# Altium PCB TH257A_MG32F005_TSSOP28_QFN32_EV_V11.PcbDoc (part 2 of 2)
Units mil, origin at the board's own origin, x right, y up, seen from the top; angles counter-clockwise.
Board outline 4094.49 x 2637.8 mil, 2 copper layers (Top Layer, Bottom Layer); 102 components, 87 nets, 480 pads, 216 vias.
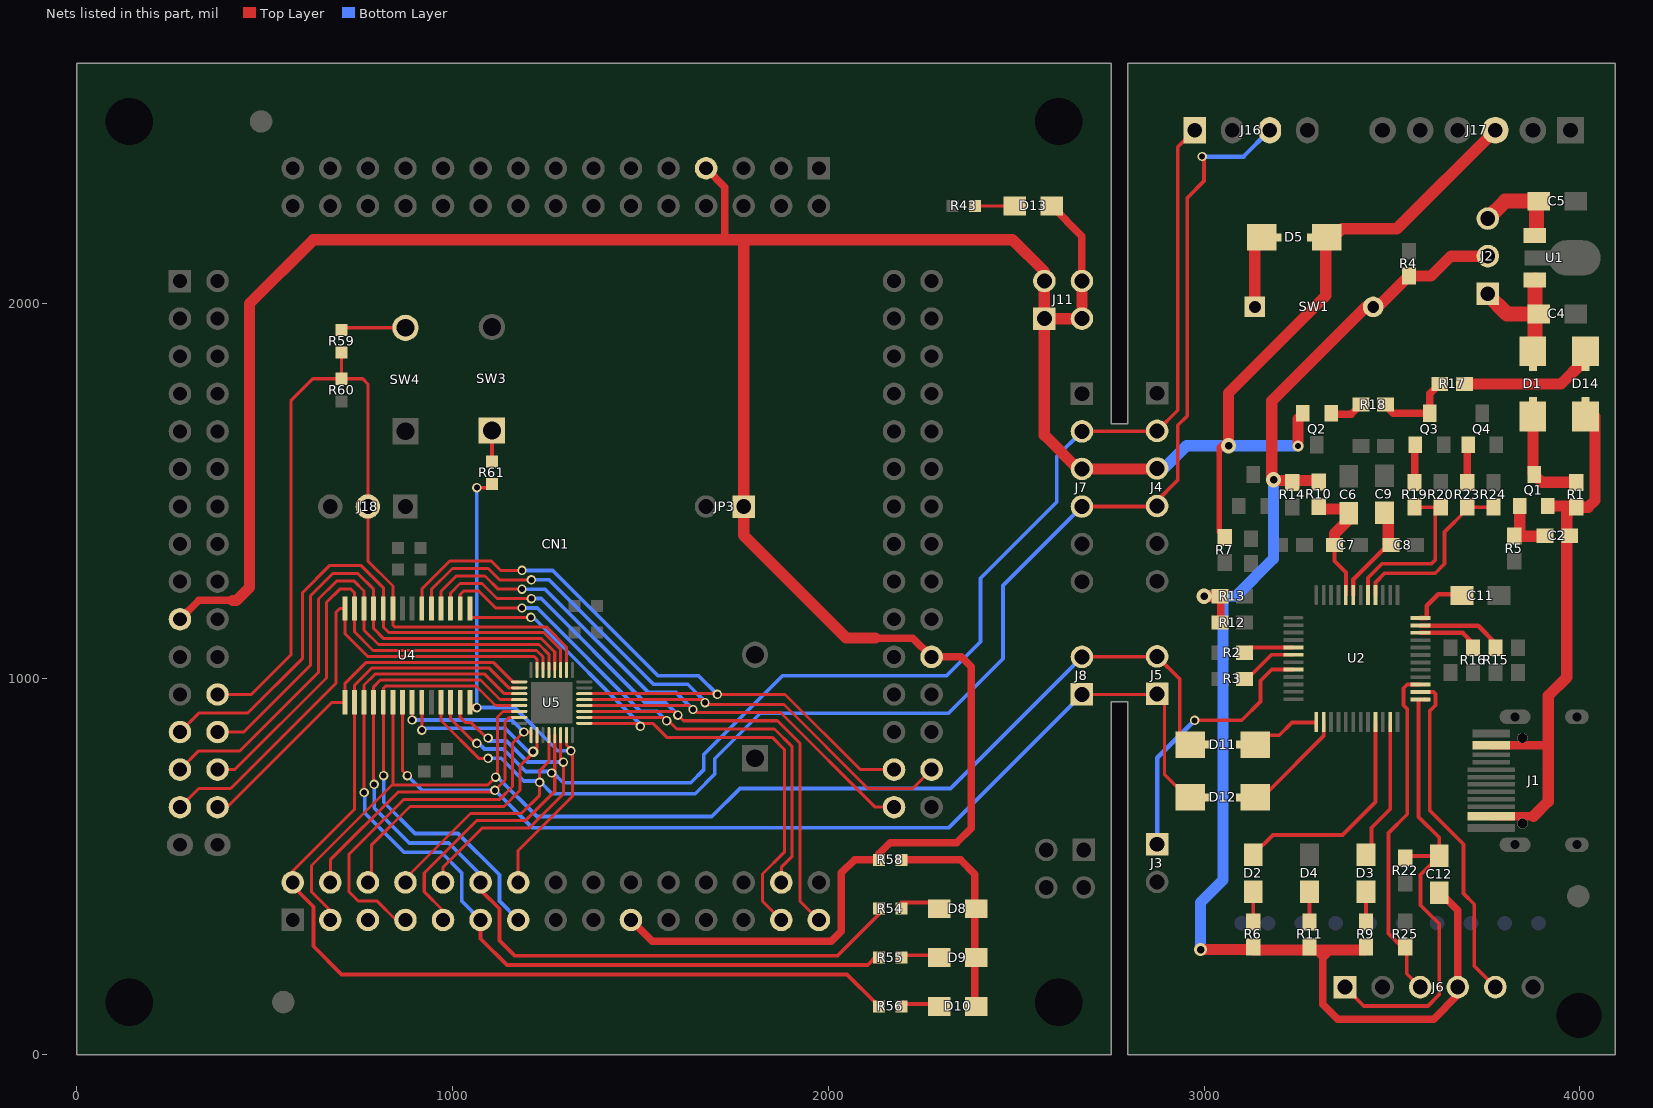
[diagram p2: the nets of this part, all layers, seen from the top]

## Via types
v1: diameter 20, hole 12, Top Layer to Bottom Layer, tented both sides, 135 vias
v2: diameter 25, hole 16, Top Layer to Bottom Layer, tented both sides, 45 vias
v3: diameter 30, hole 12, Top Layer to Bottom Layer, tented both sides, 17 vias
v4: diameter 25, hole 12, Top Layer to Bottom Layer, tented both sides, 7 vias
v5: diameter 28, hole 16, Top Layer to Bottom Layer, tented both sides, 3 vias
v6: diameter 40, hole 20, Top Layer to Bottom Layer, tented both sides, 3 vias
v7: diameter 30, hole 16, Top Layer to Bottom Layer, tented both sides, 3 vias
v8: diameter 50, hole 12, Top Layer to Bottom Layer, tented both sides, 1 vias
v9: diameter 35, hole 20, Top Layer to Bottom Layer, tented both sides, 1 vias
v10: diameter 15, hole 12, Top Layer to Bottom Layer, tented both sides, 1 vias

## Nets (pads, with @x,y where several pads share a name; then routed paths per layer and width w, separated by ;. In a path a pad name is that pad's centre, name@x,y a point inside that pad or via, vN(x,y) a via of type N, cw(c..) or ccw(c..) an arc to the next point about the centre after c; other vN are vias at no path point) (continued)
MLINK_RXD: CN1.3 D11.2 J5.2 J8.2 U4.6 U5.14 | length 3451.7
  Top Layer w8: CN1.3@675.04,358.74 675.04,383.74 625.04,433.74 625.04,503.74 839.04,717.74 841.65,717.74 ; U4.6@841.65,937.5 841.65,717.74 ; U5.14@1177.8,913.5 1134.8,913.5 1120.04,898.74 1120.04,743.74 v2(1115.04,738.74) 1094.04,717.74 841.65,717.74
  Top Layer w10: J8.2@2675.04,1058.74 J5.2@2875.04,1058.74 ; J5.2@2875.04,1060 2935.04,1000 2935.04,825 D11.2@2935.04,810
  Bottom Layer w10: v2@1117.54,741.24 1225.04,633.74 1690.04,633.74 1765.04,708.74 2325.04,708.74 J8.2@2675.04,1058.74
MLINK_TXD: CN1.4 D12.1 J5.1 J8.1 U4.7 U5.15 | length 3509.7
  Top Layer w8: CN1.4@675.04,458.74 675.04,518.74 855.04,698.74 1108.04,698.74 v2(1113.04,703.74) 1140.04,730.74 1140.04,886.47 1151.33,897.76 U5.15@1177.8,897.76 ; U4.7@867.24,937.5 867.24,755.54 v2(880.04,742.74) ; J8.1@2675.04,958.74 J5.1@2875.04,958.74 ; J5.1@2875.04,960 J5.1@2880.81,954.23 ; J5.1@2895.04,958 2895.04,745 D12.1@2948.43,691.61
  Bottom Layer w10: v2(880.04,742.74) 919.04,703.74 1104.54,703.74 1106.04,705.24 1110.29,700.99 v2@1113.04,700.99 ; v2(1113.04,703.74) 1213.04,603.74 2320.04,603.74 J8.1@2675.04,958.74
NetC2_2: C2.2 Q1.1 R5.2 | length 170
  Top Layer w30: R5.2@3825.04,1380 R5.2@3840.04,1380 ; Q1.1@3840.04,1465 Q1.1@3840.04,1460 R5.2@3840.04,1380 ; C2.2@3910.04,1380 3907,1380 R5.2@3840.04,1380
NetC6_1: C6.1 C7.2 R10.2 U2.44 | length 312.7
  Top Layer w11: C7.2@3347.04,1356.26 3347.04,1313.55 3377.23,1283.36 U2.44@3377.23,1223.13 ; C7.2@3362.59,1356.26 C7.2@3362.59,1365.26
  Top Layer w30: R10.2@3320.04,1452 3385,1452 C6.1@3385,1440.79 ; C7.2@3347.04,1356.26 3347.04,1386.45 C6.1@3383.59,1423
NetC8_2: C8.2 C9.1 U2.43 | length 261.6
  Top Layer w11: U2.43@3396.92,1223.13 3396.92,1264.18 C8.2@3490,1357.26
  Top Layer w30: C9.1@3480,1442.05 3490,1432.05 C8.2@3490,1357.26
NetC11_1: C11.1 U2.36 | length 149.7
  Top Layer w12: U2.36@3575.5,1162.16 3592.2,1162.16 3592.2,1194.68 3622.9,1225.39 C11.1@3679.94,1225.39
NetD1_1: D1.1 Q1.3 R1.2 | length 276.4
  Top Layer w30: D1.1@3875,1698.39 3875,1546.98 Q1.3@3878.04,1543.94 3898.98,1523 R1.2@3990.04,1523
NetD2_1: D2.1 R6.2 | length 97
  Top Layer w10: R6.2@3130.59,345 R6.2@3130.59,353.26 D2.1@3130.59,434.05 D2.1@3130.59,442
NetD3_1: D3.1 R9.2 | length 97
  Top Layer w10: R9.2@3430.59,345 R9.2@3430.59,353.26 D3.1@3430.59,434.05 D3.1@3430.59,442
NetD4_1: D4.1 R11.2 | length 97
  Top Layer w10: R11.2@3280.59,345 R11.2@3280.59,353.26 D4.1@3280.59,434.05 D4.1@3280.59,442
NetD5_1: D5.1 SW1.1 | length 215.1
  Top Layer w20: D5.1@3135.87,2175 D5.1@3153.39,2175 D5.1@3186.85,2175
  Top Layer w30: SW1.1@3135.08,1990 D5.1@3135.08,2154.13
NetD8_1: D8.1 D9.1 D10.1 R58.1 | length 550.6
  Top Layer w20: R58.1@2195.04,518.74 2351.9,518.74 2390,480.64 2390,388.74 2390,258.74 D10.1@2390,140.79
NetD8_2: D8.2 R54.2 | length 95.8
  Top Layer w10: 2195.04,405 D8.2@2290.79,405
NetD9_2: D9.2 R55.2 | length 95.8
  Top Layer w10: R55.2@2189.94,265 2195.04,265 D9.2@2285.73,265
NetD10_2: D10.2 R56.2 | length 95.8
  Top Layer w10: R56.2@2196.58,140 R56.2@2200,140 ; R56.2@2199.94,135 D10.2@2292.3,135
NetD11_1: D11.1 U2.13 | length 209.6
  Top Layer w10: D11.1@3121.65,810 D11.1@3136.65,825 D11.1@3151.65,840 ; D11.1@3160.04,850 3200.04,850 3234.1,884.06 U2.13@3295.96,884.06 ; U2.13@3298.49,868.45 U2.13@3298.49,885.65
NetD12_2: D12.2 U2.14 | length 287
  Top Layer w10: D12.2@3130.04,700 3136.65,700 3170.04,700 3318.18,848.14 U2.14@3318.18,885.65
NetD13_2: D13.2 R43.2 | length 105.8
  Top Layer w8: R43.2@2390.04,2258.74 D13.2@2495.83,2258.74
NetD14_2: D14.2 R17.1 | length 348.7
  Top Layer w30: R17.1@3693,1785 3945,1785 ; 3950,1785 D14.2@4009.08,1844.07 ; D14.2@3998.15,1868.15 D14.2@4010,1868.15 ; D14.2@4004.08,1844.07 D14.2@4005,1845
NetQ2_1: Q2.1 R18.2 | length 89.8
  Top Layer w20: Q2.1@3338,1703.94 3390.98,1703.94 R18.2@3417.04,1730
NetQ3_1: Q3.1 R19.2 | length 117.1
  Top Layer w20: R19.2@3560.04,1540.04 R19.2@3560.04,1523 Q3.1@3560.04,1620.53 ; Q3.1@3562.54,1620.53 Q3.1@3562.54,1623.03
NetQ3_2: Q3.2 R17.2 R18.1 | length 192.7
  Top Layer w20: R18.1@3488.04,1730 3488.04,1721.96 3503.03,1706.97 Q3.2@3600.54,1706.97 ; 3600.54,1730 3600.54,1758.54 R17.2@3627,1785
NetQ4_1: Q4.1 R23.2 | length 100
  Top Layer w20: R23.2@3700.04,1523 Q4.1@3700.04,1620.53 ; Q4.1@3702.54,1620.53 Q4.1@3702.54,1623.03
NetR15_1: R15.1 U2.35 | length 263.6
  Top Layer w12: U2.35@3575.5,1141.47 3605.04,1141.47 ; 3637.3,1141.47 3605.04,1141.47 ; R15.1@3775.59,1083 3775.59,1095 3729.12,1141.47 3605.04,1141.47
NetR16_1: R16.1 U2.34 | length 163.6
  Top Layer w12: U2.34@3575.5,1122.79 3687.8,1122.79 3715.59,1095 R16.1@3715.59,1083
NetR59_1: R59.1 SW4.2 | length 165.6
  Top Layer w10: R59.1@709.45,1934.33 SW4.2@875.04,1934.33
NetR61_2: R61.2 SW3.1 | length 82.2
  Top Layer w10: R61.2@1105.04,1578.74 SW3.1@1105.04,1660.95
P44: J6.5 U2.26 | length 900.8
  Top Layer w10: U2.26@3575.5,965.31 3610.28,965.31 3615.59,960 3615.59,930 3600.59,915 3600.59,650 3690.59,560 3690.59,429 3719.14,400.45 3719.14,235.9 J6.5@3775.04,180
P45: J6.3 R25.1 U2.27 | length 924.9
  Top Layer w10: R25.1@3539.32,290.72 3539.32,287 3539.32,215.72 J6.3@3575.04,180 ; R25.1@3540.59,292 3535.59,292 3521.03,292 3490.59,322.44 3490.59,590 3540.59,640 3540.59,920 3530.59,930 3530.59,975 3540.58,984.99 U2.27@3575.5,984.99 ; J6.3@3576.32,181.28 J6.3@3583.59,174
PA0_BOOT0: CN1.114 J18.2 R59.2 R60.1 U4.23 U5.2 | length 2436.9
  Top Layer w8: CN1.114@375.04,958.74 465.04,958.74 569.94,1063.64 569.94,1740 628.68,1798.74 R60.1@705.04,1798.74 ; R59.2@705.04,1868.74 R60.1@705.04,1798.74 ; U5.2@1303.78,1023.74 1303.78,1085 1250.04,1138.74 845.77,1138.74 841.65,1142.86 U4.23@841.65,1187.5 841.65,1247.13 775.04,1313.74 J18.2@775.04,1458.74 775.04,1784.96 761.26,1798.74 R60.1@705.04,1798.74
PA1: CN1.115 U4.24 U5.3 | length 1507.8
  Top Layer w8: CN1.115@275.04,858.74 325.04,908.74 455.04,908.74 601.4,1055.1 601.4,1230.1 673.68,1302.38 756.4,1302.38 816.06,1242.72 U4.24@816.06,1187.5 816.06,1138.45 831.52,1122.99 1243.52,1122.99 1288.03,1078.48 U5.3@1288.03,1023.74
PA2: CN1.116 U4.25 U5.4 | length 1376.5
  Top Layer w8: CN1.116@375.04,858.74 445.04,858.74 622.61,1036.31 622.61,1221.31 682.47,1281.17 747.61,1281.17 790.47,1238.31 U4.25@790.47,1187.5 790.47,1134.04 817.27,1107.24 1236.99,1107.24 1272.28,1071.95 U5.4@1272.28,1023.74
PA3: CN1.117 U4.26 U5.5 | length 1490.7
  Top Layer w8: CN1.117@271.02,758.74 CN1.117@275.04,758.74 325.04,808.74 435.04,808.74 643.83,1017.53 643.83,1212.53 691.25,1259.95 738.83,1259.95 764.88,1233.9 U4.26@764.88,1187.5 764.88,1129.63 803.02,1091.5 1230.47,1091.5 1256.54,1065.43 U5.5@1256.54,1023.74
PA4: CN1.118 U4.27 U5.6 | length 1353
  Top Layer w8: CN1.118@375.04,758.74 421.02,758.74 665.04,1002.76 665.04,1203.74 700.04,1238.74 730.04,1238.74 739.29,1229.49 U4.27@739.29,1187.5 739.29,1125.22 788.76,1075.75 1223.95,1075.75 1240.79,1058.91 U5.6@1240.79,1023.74
PA5: CN1.119 U4.28 U5.7 | length 1403.3
  Top Layer w8: CN1.119@275.04,658.74 325.04,708.74 410.04,708.74 690.04,988.74 690.04,1177.5 700.04,1187.5 U4.28@713.7,1187.5 713.7,1120.81 774.51,1060 1217.42,1060 1225.04,1052.38 U5.7@1225.04,1023.74
PA6: CN1.120 U4.1 U5.9 | length 1013.2
  Top Layer w8: CN1.120@375.04,658.74 400.04,658.74 678.8,937.5 U4.1@713.7,937.5 713.7,987.4 770.55,1044.25 1108.53,1044.25 1160.54,992.24 U5.9@1177.8,992.24
PA7: CN1.2 R56.1 U4.2 U5.10 | length 2845.5
  Top Layer w8: CN1.2@575.04,468.74 CN1.2@575.04,458.74 575.04,488.74 739.29,652.99 U4.2@739.29,937.5 739.29,982.99 784.8,1028.5 1098,1028.5 1150.01,976.5 U5.10@1177.8,976.5
  Top Layer w10: CN1.2@575.04,458.74 575.04,448.74 630.04,393.74 630.04,288.74 705.04,213.74 2050.04,213.74 2123.78,140 2135.04,140 R56.1@2140,140
PA10: CN1.5
PA11: CN1.6 U4.9 U5.18 | length 1115.5
  Top Layer w8: CN1.6@775.04,458.74 CN1.6@782.67,466.37 ; CN1.6@785.3,463.74 785.3,559 887.04,660.74 1137.04,660.74 1180.04,703.74 1180.04,768.74 1216.54,805.24 1225.04,813.74 U5.18@1225.04,850.51 ; v2(918.43,863.74) U4.9@918.43,937.5
  Bottom Layer w10: v2(918.43,863.74) 923.43,868.74 1140.04,868.74 v5@1205.04,803.74
  other v5: 1215.04,806.74
PA12: CN1.7 U4.8 U5.17 | length 1332.5
  Top Layer w8: CN1.7@875.04,358.74 850.04,358.74 800.04,408.74 750.04,408.74 725.04,433.74 725.04,533.74 871.04,679.74 1126.04,679.74 1160.04,713.74 1160.04,828.62 1190.04,858.62 1209.29,858.62 U5.17@1209.29,850.51 ; v2(892.83,890.74) U4.8@892.83,937.5
  Bottom Layer w10: v2(892.83,890.74) 1158.04,890.74 v2(1190.04,858.74)
PA13_SWDIO: CN1.8 J4.4 J7.4 J16.3 U4.11 U5.20 | length 4299.1
  Top Layer w8: CN1.8@875.04,458.74 CN1.8@875.04,468.74 ; CN1.8@875.04,478.74 CN1.8@875.04,468.74 ; U4.11@969.61,937.5 969.61,889.17 1070.04,788.74 v2(1095.04,788.74) ; U5.20@1256.54,850.51 1256.54,780.24 1232.04,755.74 v2(1232.04,724.74) 1232.04,690.74 1183.04,641.74 1048.04,641.74 CN1.8@875.04,468.74
  Top Layer w10: J7.4@2675.04,1458.74 J4.4@2860.04,1458.74 ; J4.4@2868.04,1467 2930.04,1529 2930.04,1675 2955.04,1700 2955.04,2280 3000.04,2325 v2@3000.04,2390
  Bottom Layer w10: v2(1095.04,788.74) 1130.04,788.74 1190.04,728.74 v2@1232.04,728.74 ; v2@1232.04,727.74 1233.54,726.24 1265.04,694.74 1646.05,694.74 1698.04,746.73 1698.04,787.73 1819.05,908.74 2320.04,908.74 2465.04,1053.74 2465.04,1248.74 J7.4@2675.04,1458.74
  Bottom Layer w12: v2(2995.04,2390) 3105.04,2390 J16.3@3175.04,2460
PA14_SWCLK: CN1.9 J4.2 J7.2 J16.1 U4.12 U5.21 | length 4146.3
  Top Layer w8: CN1.9@975.04,358.74 975.04,383.74 925.04,433.74 925.04,483.74 1064.04,622.74 1194.04,622.74 1272.28,700.98 1272.28,749.74 U5.21@1272.28,850.51 ; U4.12@995.2,937.5 995.2,893.58 v2@1062.54,826.24
  Top Layer w10: J7.2@2675.04,1658.74 J4.2@2875.04,1658.74 ; J4.2@2875.04,1660 2930.04,1715 2930.04,2415 J16.1@2975.04,2460
  Bottom Layer w10: v2@1067.54,831.24 1085.04,813.74 1135.04,813.74 1195.04,753.74 1264.04,753.74 1265.12,753.74 1266.58,752.28 1295.12,723.74 1634.04,723.74 1669.04,758.74 1669.04,799.74 1878.04,1008.74 2315.04,1008.74 2405.04,1098.74 2405.04,1267.74 2608.04,1470.74 2608.04,1591.74 J7.2@2675.04,1658.74
  other v2: 1264.04,749.74 1065.04,828.74
PA15: CN1.10 U4.13 U5.22 | length 962.6
  Top Layer w8: CN1.10@975.04,458.74 975.04,498.74 1080.04,603.74 1205.04,603.74 1295.67,694.38 1295.67,778.1 v2(1295.04,778.74) 1288.03,785.75 U5.22@1288.03,850.51 ; U4.13@1020.79,937.5 1020.79,897.99 1035.04,883.74 1050.04,883.74 1093.04,840.74 v2@1095.04,838.74
  Bottom Layer w10: v2@1095.04,835.12 1143.66,835.12 1200.04,778.74 v2(1295.04,778.74)
  other v2: 1095.04,842.74
PASS: D3.2 U2.23 | length 376.3
  Top Layer w10: D3.2@3445.59,530 3445.59,532.47 3445.59,604.16 3495.34,653.92 U2.23@3495.34,885.65
PB0: CN1.11 R55.1 U4.3 U5.11 | length 2401.5
  Top Layer w8: v2(764.88,697.74) U4.3@764.88,937.5 764.88,983.58 794.06,1012.76 1086.02,1012.76 1138.03,960.75 U5.11@1177.8,960.75
  Top Layer w10: CN1.11@1075.04,358.74 1075.04,308.74 1145.04,238.74 2105.04,238.74 R55.1@2130.04,263.74
  Bottom Layer w10: v2@766.63,697.74 766.63,643.15 871.04,538.74 970.04,538.74 1025.04,483.74 1025.04,408.74 CN1.11@1075.04,358.74
PB1: CN1.12 R54.1 U4.4 U5.12 | length 2378.3
  Top Layer w8: v2@790.47,719.74 U4.4@790.47,937.5 790.47,979.17 808.31,997.01 1074.48,997.01 1126.49,945 U5.12@1177.8,945
  Top Layer w10: CN1.12@1075.04,458.74 1075.04,438.74 1125.04,388.74 1125.04,303.74 1165.04,263.74 2025.04,263.74 2135.04,373.74 R54.1@2135.04,388.74
  Bottom Layer w10: v2(791.83,719.74) 791.83,656.94 885.04,563.74 990.04,563.74 1075.04,478.74 CN1.12@1075.04,458.74
PB2: CN1.13 U4.5 U5.13 | length 1221.6
  Top Layer w8: v2@816.06,738.74 816.06,742.74 U4.5@816.06,937.5 816.06,974.76 822.56,981.26 1062.52,981.26 1114.53,929.25 U5.13@1177.8,929.25
  Bottom Layer w10: v2(817.04,742.74) 817.04,671.74 900.04,588.74 1015.04,588.74 1125.04,478.74 1125.04,408.74 CN1.13@1175.04,358.74
PB3: CN1.14 R61.1 U4.14 U5.23 | length 1406.2
  Top Layer w8: U4.14@1045.04,928.74 1046.38,928.74 v2@1065.04,928.74 ; CN1.14@1175.04,458.74 1175.04,543.74 1320.04,688.74 1320.04,807.74 1317.04,810.74 1303.78,824 U5.23@1303.78,850.51 ; CN1.14@1190.04,458.74 CN1.14@1190.04,463.74
  Top Layer w10: v2(1065.04,1508.74) R61.1@1105.04,1508.74
  Bottom Layer w10: v2(1065.04,1508.74) v2(1065.04,923.74) 1165.04,923.74 1280.04,808.74 v2(1315.04,808.74)
PB4: CN1.27 U4.15 U5.25 | length 1629.3
  Top Layer w8: U4.15@1045.04,1163.74 1046.38,1163.74 v2(1208.7,1163.74) ; U4.15@1045.04,1213.74 U4.15@1046.38,1213.74 ; U5.25@1351.02,882.01 1500.04,882.01 1532.77,882.01 1570.04,844.74 1850.76,844.74 1883.04,812.46 1883.04,538.75 1825.04,480.75 1825.04,408.74 CN1.27@1875.04,358.74
  Bottom Layer w10: v2@1219.06,1160.11 1502.73,876.43 v2@1505.42,873.74
  other v2: 1500.04,873.74
PB5: CN1.28 U4.16 U5.26 | length 1710.5
  Top Layer w8: U4.16@1020.79,1187.5 1020.79,1224.49 1030.04,1233.74 1070.19,1233.74 1115.19,1188.74 v2(1185.04,1188.74) ; U5.26@1351.02,897.76 1566.02,897.76 1572.54,891.24 1597.04,866.74 1857.04,866.74 1903.04,820.74 1903.04,526.74 1875.04,498.74 CN1.28@1875.04,458.74 CN1.28@1875.04,478.74
  Bottom Layer w10: v2(1185.04,1188.74) 1225.78,1188.74 1500.78,913.74 1545.04,913.74 v2(1570.04,888.74)
PB6: CN1.29 U4.17 U5.27 | length 1901.3
  Top Layer w8: U4.17@995.2,1187.5 995.2,1228.9 1020.04,1253.74 1078.47,1253.74 1118.47,1213.74 v2(1210.04,1213.74) ; U5.27@1351.02,913.5 1590.04,913.5 1599.92,903.62 1614.8,888.74 1865.04,888.74 1925.04,828.74 1925.04,408.74 CN1.29@1975.04,358.74
  Bottom Layer w10: v2(1210.04,1213.74) 1236.13,1213.74 1511.13,938.74 1565.04,938.74 v2(1600.04,903.74)
PB7: CN1.32 U4.18 U5.28 | length 1815.2
  Top Layer w8: U4.18@969.61,1187.5 969.61,1233.31 1010.04,1273.74 1086.76,1273.74 1121.76,1238.74 v2(1185.04,1238.74) ; U5.28@1351.02,929.25 1629.53,929.25 v2(1640.04,918.74) ; v2@1641.54,920.24 1651.03,910.74 1873.04,910.74 2125.04,658.74 CN1.32@2175.04,658.74
  Bottom Layer w10: v2(1185.04,1238.74) 1246.49,1238.74 1521.49,963.74 1595.04,963.74 v2(1640.04,918.74)
PB8: CN1.33 U4.19 U5.29 | length 2004
  Top Layer w8: U4.19@944.02,1187.5 944.02,1237.72 1000.04,1293.74 1095.04,1293.74 1125.04,1263.74 v2(1210.04,1263.74) ; U5.29@1351.02,945 1668.78,945 1674.54,939.24 v2@1682.05,931.73 ; v2@1680.04,931.73 v2@1682.05,931.73 ; CN1.33@2275.04,758.74 2225.04,708.74 2105.04,708.74 1882.05,931.73 v2@1682.05,931.73
  Bottom Layer w10: v2(1210.04,1263.74) 1256.84,1263.74 1534.84,985.75 1626.02,985.75 1673.54,938.24 v2@1680.04,931.73
  other v2: 1672.04,936.74
PB9: CN1.34 U4.20 U5.30 | length 1934.4
  Top Layer w8: U4.20@918.43,1187.5 918.43,1239.13 993.04,1313.74 1103.32,1313.74 1128.32,1288.74 v2(1185.04,1288.74) ; U5.30@1351.02,960.75 v2@1698.03,960.75 ; v2@1702.54,956.24 v2@1700.04,958.74 ; v2@1705.04,960.75 v2@1698.03,960.75 ; CN1.34@2175.04,758.74 2085.04,758.74 1885.04,958.74 v2(1705.04,958.74) v2@1700.04,958.74 ; v2@1698.03,960.75 v2@1700.04,958.74
  Bottom Layer w10: v2(1185.04,1288.74) 1267.2,1288.74 1547.2,1008.74 1655.04,1008.74 v2(1705.04,958.74)
RST: C12.2 J6.1 R22.2 U2.25 | length 1228.1
  Top Layer w10: J6.1@3375.04,180 3425.04,130 3595.59,130 3625.59,160 3625.59,348 3575.59,398 3575.59,479.21 C12.2@3625.59,529.21 ; R22.2@3541.8,529.21 C12.2@3625.59,529.21 ; U2.25@3575.59,945 3570.59,940 3570.59,633 3625.59,578 C12.2@3625.59,529.21 ; U2.25@3585.04,945.62 U2.25@3594.42,945.62
RST_CTRL_51: R19.1 R20.1 U2.41 | length 455
  Top Layer w10: U2.41@3436.29,1223.13 3436.29,1269.12 3473.42,1306.26 3605,1306.26 3615.04,1316.3 R20.1@3615.04,1457 ; R19.1@3560.04,1457 R20.1@3615.04,1457 ; R20.1@3630.04,1457 R20.1@3615.04,1457
RST_CTRL_ARM: R23.1 R24.1 U2.40 | length 474.6
  Top Layer w10: U2.40@3455.97,1223.13 3455.97,1256.93 3480.3,1281.26 3615,1281.26 3640.04,1306.3 3640.04,1391.3 R23.1@3697.5,1448.76 ; R23.1@3700.04,1457 R24.1@3770.04,1457
TOOL_OPTION0: R2.1 U2.5 | length 135.2
  Top Layer w10: R2.1@3108.04,1070 3121.96,1083.92 U2.5@3237.52,1083.92
TOOL_OPTION1: R3.1 U2.6 | length 156.1
  Top Layer w10: R3.1@3108.04,1000 3115.04,1000 3179.27,1064.23 U2.6@3237.52,1064.23
USBOK: D2.2 U2.21 | length 596.3
  Top Layer w10: D2.2@3130.59,532.47 3183.12,585 3368.04,585 3455.97,672.94 U2.21@3455.97,885.65
VCC_USB: C2.1 D14.1 J1.A4 J1.A9 J1.M5 J1.M6 Q1.2 R1.1 | length 1456.2
  Top Layer w22: J1.A4@3763.84,634.61 3847.24,634.61 3876.67,634.61 ; J1.A9@3763.84,823.62 3847.24,823.62 3915.59,823.62
  Top Layer w30: 3876.67,634.61 3915.59,673.54 3915.59,823.62 3915.59,955 3964.92,1004.33 3964.92,1381.26 3964.92,1446.88 ; Q1.2@3915.04,1460 3967.04,1460 ; R1.1@3980.04,1457 R1.1@3990.04,1457 4022,1457 4040,1475 D14.1@4040,1698.39
VCP_OPTION: J3.1 U2.8 | length 722
  Top Layer w10: v2(2975,890) 3100.04,890 3150.04,940 3150.04,995 3179.9,1024.86 U2.8@3237.52,1024.86
  Bottom Layer w12: J3.1@2875.04,560 2875.04,790.04 v2(2975,890)
VDD: C12.1 J2.2 J6.4 R4.1 R6.1 R9.1 R10.1 R11.1 R12.1 R13.1 R14.2 SW1.2 | length 3958.9
  Top Layer w12: R11.1@3289.78,279.52 3290.3,279 3315.59,253.71 3315.94,253.36 ; 3315.95,251.65 3342.11,277.81
  Top Layer w20: v6@3003.11,1215 R13.1@3037.04,1215 ; v6@3008.11,1225 R13.1@3042.04,1225 ; R12.1@3044.04,1150 R13.1@3044.04,1219.56 ; 3315.59,279 3315.59,253.71 3315.59,135 3355.59,95 3610.59,95 3675.04,159.45 J6.4@3675.04,180 3675.04,384.55 3635.59,424 C12.1@3635.59,430.79
  Top Layer w30: v9(2990.59,280) R6.1@3130.59,280 ; R6.1@3130.59,279 3280.59,279 3290.3,279 3315.59,279 R9.1@3430.59,279 ; R14.2@3240,1528 3235,1528 3187,1528 v6(3185,1530) 3180,1535 3180,1740 3428.75,1988.75 3438.83,1988.75 3443.81,1983.77 3450.04,1977.54 3456.27,1983.77 3544.5,2072 R4.1@3545.04,2072 3604,2072 3657,2125 J2.2@3755.04,2125 ; R14.2@3245,1528 R10.1@3305,1528
  Bottom Layer w30: v9(2990.59,280) 2990.59,405 3050.59,465 3050.59,1220 ; v6(3000.04,1220) 3050.59,1220 ; 3050.59,1220.1 3050.59,1220 ; v6(3185,1530) 3185,1319.96 3085.04,1220 3050.59,1220
VDD3: C5.1 J2.3 U1.1 | length 231.2
  Top Layer w40: J2.3@3755.04,2225 3801.3,2271.26 C5.1@3885,2271.26 ; U1.1@3885,2195 C5.1@3885,2271.26 ; C5.1@3890.79,2271.26 C5.1@3885,2271.26
VDD5: C4.1 D1.2 J2.1 U1.3 | length 318.5
  Top Layer w40: J2.1@3753.56,2023.52 3805.83,1971.26 C4.1@3880,1971.26 ; D1.2@3880,1901.61 C4.1@3880,1971.26 ; U1.3@3880,2061.26 C4.1@3880,1971.26 ; C4.1@3890.79,1971.26 C4.1@3880,1971.26
VDUT: CN1.19 CN1.39 CN1.67 CN1.109 D5.2 D13.1 J4.3 J7.3 J11.1 J11.2 J11.3 J11.4 J17.3 JP3.1 Q2.2 R7.1 R58.2 | length 9765.1
  Top Layer w15: R7.1@3055.04,1376 3040.04,1391 3040.04,1615.5 3055.04,1630.5 3065.04,1640.5 ; v6@3072.79,1612.75 v6@3075.04,1615
  Top Layer w20: CN1.109@275.04,1158.74 325.04,1208.74 415.04,1208.74 ; CN1.19@1475.04,358.74 1532.14,301.64 2007.94,301.64 2035.04,328.74 2035.04,483.74 2070.04,518.74 R58.2@2135.04,518.74 2135.04,534.74 2165.04,564.74 2342.14,564.74 2379.94,602.54 2379.94,1032.74 2353.94,1058.74 CN1.39@2275.04,1058.74 2225.04,1108.74 2125.04,1108.74 ; CN1.67@1675.04,2358.74 1725.04,2308.74 1725.04,2168.74 ; D13.1@2594.25,2258.74 2675.04,2177.95 J11.4@2675.04,2058.74 ; D5.2@3293.15,2175 D5.2@3326.61,2175 D5.2@3344.13,2175
  Top Layer w30: 415.04,1208.74 425.04,1208.74 460.04,1243.74 460.04,1998.74 630.04,2168.74 1725.04,2168.74 1775.04,2168.74 ; 2125.04,1108.74 2048.04,1108.74 1775.04,1381.74 JP3.1@1775.04,1458.74 1775.04,2168.74 ; J7.3@2675.04,1548.74 2670.04,1553.74 J7.3@2665.04,1558.74 ; J11.4@2675.04,2058.74 J11.3@2675.04,1958.74 J11.1@2575.04,1958.74 ; J4.3@2875.04,1558.74 J7.3@2675.04,1558.74 J7.3@2665.04,1558.74 ; v6(3065.04,1620.5) 3065.04,1640.5 3065.04,1760.91 3324.13,2020 D5.2@3324.13,2170 ; v7@3250,1620.5 3250,1690.94 Q2.2@3263,1703.94 ; D5.2@3339.13,2170 3344.13,2175 3366.89,2197.76 3512.8,2197.76 J17.3@3775.04,2460 ; 1775.04,2168.74 2490.04,2168.74 2575.04,2083.74 J11.2@2575.04,2058.74 J11.1@2575.04,1958.74 ; J11.1@2575.04,1958.74 2575.04,1648.74 J7.3@2665.04,1558.74
  Bottom Layer w30: J4.3@2893.07,1560.5 2953.07,1620.5 v6(3065.04,1620.5) v7@3250,1620.5
  other v7: 3250,1620
pads on no net: CN1.1 CN1.15 CN1.16 CN1.18 CN1.20 CN1.21 CN1.22 CN1.23 CN1.24 CN1.25 CN1.26 CN1.30 CN1.31 CN1.35 CN1.36 CN1.37 CN1.38 CN1.40 CN1.42 CN1.43 CN1.44 CN1.45 CN1.46 CN1.47 CN1.48 CN1.49 CN1.50 CN1.51 CN1.52 CN1.53 CN1.54 CN1.55 CN1.56 CN1.57 CN1.58 CN1.59 CN1.60 CN1.61 CN1.62 CN1.63 CN1.64 CN1.65 CN1.66 CN1.68 CN1.70 CN1.71 CN1.72 CN1.73 CN1.74 CN1.75 CN1.76 CN1.77 CN1.78 CN1.79 CN1.80 CN1.81 CN1.82 CN1.83 CN1.84 CN1.85 CN1.86 CN1.87 CN1.88 CN1.89 CN1.90 CN1.91 CN1.92 CN1.93 CN1.94 CN1.95 CN1.96 CN1.97 CN1.98 CN1.99 CN1.100 CN1.101 CN1.102 CN1.103 CN1.104 CN1.105 CN1.106 CN1.108 CN1.110 CN1.111 CN1.112 CN1.113 CN1.121 CN1.122 J1.A5 J1.A8 J1.B5 J1.B8 J6.6 J7.1 U2.1 U2.2 U2.3 U2.4 U2.7 U2.24 U2.28 U2.29 U2.30 U2.32 U2.37 U2.38 U2.39 U2.46 U5.8 U5.16 U5.24 U5.32 U5.33

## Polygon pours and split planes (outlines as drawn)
GND_POWER on Bottom Layer "Top Layer-No Net" (hatched 90Degree grid 10 track 10, remove dead copper, pour order 1001): 25,20 4070,20 4070,2593.74 25,2593.74
GND_POWER on Top Layer "Top Layer-No Net" (hatched 90Degree grid 10 track 10, remove dead copper, pour order 1001): 25,20 4070,20 4070,2593.74 25,2593.74

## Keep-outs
Top Layer:
  circle w5: c3995.59,421.9 r59.06
  circle w5: c491,2483.43 r59.06
  circle w5: c550,140 r59.06
Keep-Out Layer:
  circle w7.88: c140,2483.43 r133.86
  circle w7.88: c2613.39,2483.43 r133.86
  circle w7.88: c2613.39,140 r133.86
  circle w7.88: c140,140 r133.86
  lines w15: 2796.69,938.74 2753.39,938.74 2753.39,0 0,0 0,2637.8 2753.39,2637.8 2753.39,1678.74 2796.69,1678.74 ; 4094.49,1.26 4094.49,2639.06

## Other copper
Top Layer:
  pour cut-out: 2710,2623.74 2830,2623.74 2830,0 2710,0
Bottom Layer:
  pour cut-out: 2710,2625 2830,2625 2830,0 2710,0

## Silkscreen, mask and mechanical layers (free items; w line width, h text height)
Top Overlay:
  circle w10: c140,140 r137.8
  circle w4: c2613.39,140 r137.8
  circle w10: c2613.39,2483.43 r137.8
  circle w10: c140,2483.43 r137.8
  region: 2877.11,264.05 2902.77,335.95 2887.11,334.05 2887.11,394.05 2867.11,394.05 2867.11,334.05 2852.77,335.95
  region: 2614.4,1059.29 2567.5,1084.94 2569.4,1069.29 2519.4,1069.29 2519.4,1049.29 2569.4,1049.29 2567.5,1034.94
  region: 2520.95,947.11 2567.86,921.46 2565.95,937.11 2615.95,937.11 2615.95,957.11 2565.95,957.11 2567.86,971.46
  text "GND" at 1595.04,2423.74 h50 r90
  text "VDUT" at 1695.04,2423.74 h50 r90
  text "When J16 Open," at 2840.04,2335 h45
  text "SCL" at 3895.04,2320 h35 r90
  text "CLK" at 3995.04,2320 h35 r90
  text "RST" at 3495.04,2310 h37 r90
  text "GND" at 3595.04,2305 h37 r90
  text "SDA" at 3695.04,2305 h37 r90
  text "VCC" at 3795.04,2305 h37 r90
  text "SW1 must be off." at 2840.04,2260 h45
  text "VDD3" at 3565,2201.9 h37
  text "Power" at 2450.04,2158.74 h50
  text "VDD" at 3595.04,2105 h37
  text "Key1" at 795.04,2048.74 h50
  text "Key2" at 1035.04,2048.74 h50
  text "VDD5" at 3565,1991.9 h37
  text "2024.07" at 1822.04,1932.74 h35
  text "TH257A_MG32F005" at 1243.04,1851.74 h50
  text "Power On" at 3375.04,1845 h45
  text "VDUT" at 2515.04,1840.64 h50
  text "Power Off" at 2945.04,1840 h45
  text "_TSSOP28_QFN32_EV_V11" at 1200.04,1759.74 h45
  text "SCL" at 2530.04,1643.74 h33
  text "VDUT" at 2495.04,1538.74 h33
  text "SDA" at 2525.04,1443.74 h33
  text "GND" at 2525.04,1338.74 h33
  text "RST" at 2530.04,1238.74 h33
  text "GND" at 85.04,1228.74 h50
  text "RESET" at 1715.04,1173.74 h50
  text "GND" at 2340.04,1138.74 h50
  text "PA8_TX" at 2490,1135 h38
  text "VDUT" at 45,1130.64 h50
  text "↓" at 2995.04,1060 h100 r90
  text "VDUT" at 2340.04,1033.74 h50
  text "↓" at 2945.04,960 h100 r270
  text "PA0" at 439.94,933.74 h50
  text "PA9_RX" at 2500,850 h38
  text "PA2" at 440.04,830.64 h50
  text "PA1" at 95.04,828.74 h50
  text "PB9" at 1985.04,733.74 h50
  text "PB8" at 2340.04,733.74 h50
  text "PA4" at 440.04,730.64 h50
  text "PA3" at 75.04,728.74 h50
  text "PB7" at 1985.04,633.74 h50
  text "PA6" at 440.04,630.64 h50
  text "PA5" at 75.04,628.74 h50
  text "PA7" at 485,530 h50
  text "PA9" at 695.04,523.74 h50 r90
  text "PA11" at 795.04,523.74 h50 r90
  text "PA13" at 895.04,523.74 h50 r90
  text "PA15" at 995.04,523.74 h50 r90
  text "PB1" at 1100.04,523.74 h50 r90
  text "PB3" at 1200.04,523.74 h50 r90
  text "PB5" at 1900.04,523.74 h50 r90
  text "GND" at 2545,320 h50
  text "J3" at 2835.04,201.9 h45
  text "PB0" at 1100.04,168.74 h50 r90
  text "PB2" at 1200.04,168.74 h50 r90
  text "GND" at 1405.04,168.74 h50 r90
  text "PB4" at 1900.04,168.74 h50 r90
  text "PB6" at 2000.04,168.74 h50 r90
  text "PA8" at 695.04,163.74 h50 r90
  text "Open Disable VCP." at 2815.59,130 h40
  text "VDUT" at 1500.04,124.45 h50 r90
  text "PA10" at 795.04,123.74 h50 r90
  text "PA12" at 900,120 h50 r90
  text "PA14" at 1005,120 h50 r90
  text "Short Enable VCP." at 2815.59,35 h40
Mechanical 1:
  circle w7.88: c2775.04,1613.74 r27
  circle w7.88: c2775.04,1503.74 r27
  circle w7.88: c2775.04,1416.74 r25
  circle w7.88: c2775.04,1298.74 r25
  circle w7.88: c2775.04,1008.74 r33
  lines w7.88: 2753.39,1078.74 2753.39,1232.74 2796.69,1232.74 2796.69,1078.74 2753.39,1078.74
  lines w8.88: 0,0 0,2637.8 2753.39,2637.8 2753.39,1678.74 2796.69,1678.74 2796.69,2637.8 4094.49,2637.8 4094.49,0 2796.69,0 2796.69,938.74 2753.39,938.74 2753.39,0 0,0
Mechanical 2:
  lines w6: 2775.04,1031.74 2775.04,1008.74 2798.04,1008.74 ; 2775.04,1321.74 2775.04,1298.74 2798.04,1298.74 ; 2775.04,1441.74 2775.04,1418.74 2798.04,1418.74 ; 2775.04,1526.74 2775.04,1503.74 2798.04,1503.74 ; 2775.04,1636.74 2775.04,1613.74 2798.04,1613.74

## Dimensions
0,0 to 0,2637.8 on Top Overlay
0,0 to 4094.49,0 on Top Overlay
